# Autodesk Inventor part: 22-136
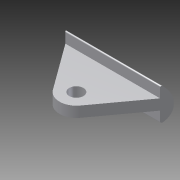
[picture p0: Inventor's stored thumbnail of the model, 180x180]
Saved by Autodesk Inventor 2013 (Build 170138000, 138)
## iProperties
Created: 2004-11
Part Number: 22-136
Document SubType Name: Modeling
Designer: Autodesk, Inc.
Manufacturer: Standard
Standards Organization: Custom
Description: RUNNER
Catalog Web Link: http://www.parker.com/ead/cm1.asp?cmid=809
Vendor: PARKER IPS
Mass: 8.75916 g
Surface Area: 44.4824 cm^2
Volume: 8.75916 cm^3
Density: 1 g/cm^3
Material: Allgemein
CAGE: 1LJX3
Dept. ID: Product Design
Description #2: ---
Finish #1: ---
Finish #2: ---
Material ID: ---
Project Number: ---
Description: Tool Runner
Order Number: 22-136
Selection: Runner
Supplier: Parker Hannifin Corp., Industrial Profile Systems Div.
Author: Autodesk, Inc.
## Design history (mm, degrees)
feature "Base1"
node "Tool Axis"
node "MidPlane"
body "Solid1"
other parameters: "d0" = 0
